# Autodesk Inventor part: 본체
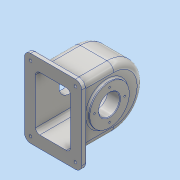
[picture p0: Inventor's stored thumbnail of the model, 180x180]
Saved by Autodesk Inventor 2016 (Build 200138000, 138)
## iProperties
Created: 2018-11
Part Number: 본체
Material: 알루미늄 6061
Document SubType Name: Modeling
Designer: user
Density: 2.7 g/cm^3
Appearance: 알루미늄 - 평지
Mass: 1136.18 g
Surface Area: 1200.87 cm^2
Volume: 420.806 cm^3
Author: user
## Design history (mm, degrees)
sketch "스케치1"
  geometry: L1 (-55, 75)-(55, 75); L2 (55, 75)-(55, -75); L3 (55, -75)-(-55, -75); L4 (-55, -75)-(-55, 75); L5 (-55, 75)-(55, -75); L6 (55, 75)-(-55, -75); 1 further point
  constraints: 12 end point, 2 midpoint, 2 parallel, 1 horizontal, 1 perpendicular
  dimensions: "d0" = 150 distance of L1.end L2.end; "d1" = 110 distance of L1.start L1.end
extrude "돌출1" new body sketch "스케치1" distance "d2" = 10; taper "d3" = 0 deg
node "작업 평면1"
sketch "스케치5"
  geometry: L1 (78, 58)-(10, 58); L2 (10, -75)-(10, 75) reference; L3 (78, -58)-(10, -58); A1 r 58 centre (78, 0) between (78, -58) and (78, 58); 1 further point
  constraints: 4 end point, 2 point on circle, 2 point on line, 2 tangent, 1 centre point, 1 horizontal, 1 horizontal alignment, 1 perpendicular
  dimensions: "d5" = 78 distance of point (0, 0) A1.centre; "d6" = 116 diameter of A1
extrude "돌출2" join sketch "스케치5" stored distance "d7" = 77; taper "d8" = 0 deg
sketch "스케치6"
  geometry: L1 (75, 0)-(-75, 0) reference; C1 r 38 at (0, 65); 2 further points
  constraints: 1 centre point, 1 midpoint, 1 vertical alignment
  dimensions: "d11" = 76 diameter of C1; "d12" = 65 distance from line of L1 C1.centre
extrude "돌출3" join sketch "스케치6" distance "d13" = 5; taper "d14" = 0 deg
sketch "스케치7"
  geometry: L1 (75, 0)-(-75, 0) reference; C1 r 38 at (0, 65); 2 further points
  constraints: 1 centre point, 1 midpoint, 1 vertical alignment
  dimensions: "d15" = 76 diameter of C1; "d16" = 65 distance from line of L1 C1.centre
extrude "돌출4" join sketch "스케치7" distance "d17" = 10; taper "d18" = 0 deg
sketch "스케치11"
  geometry: L1 (10, -58)-(78, -58) reference; L2 (78, 58)-(10, 58) reference; L3 (0, 52)-(78, 52); L4 (78, -52)-(0, -52); L5 (0, -75)-(0, 75) reference; L6 (0, -52)-(0, 52); A1 r 58 centre (78, 0) between (78, -58) and (78, 58) reference; A2 r 52 centre (78, 0) between (78, -52) and (78, 52); 1 further point
  constraints: 6 end point, 2 horizontal, 2 point on circle, 2 point on line, 2 tangent, 1 centre point, 1 collinear
  dimensions: "d31" = 6 radial gap between concentric circles of A1 A2
extrude "돌출6" cut sketch "스케치11" stored distance "d32" = 67; taper "d33" = 0 deg
sketch "스케치12"
  geometry: C1 r 20 at (0, 0); C2 r 38 at (0, 0) reference; 1 further point
  constraints: 1 centre point, 1 concentric
  dimensions: "d34" = 40 diameter of C1
extrude "돌출7" cut sketch "스케치12" distance "d35" = 24; taper "d36" = 0 deg
sketch "스케치13"
  geometry: C1 r 20 at (0, 0); C2 r 38 at (0, 0) reference; 1 further point
  constraints: 1 centre point, 1 concentric
  dimensions: "d37" = 40 diameter of C1
extrude "돌출8" cut sketch "스케치13" distance "d38" = 15; taper "d39" = 0 deg
node "작업 평면3"
sketch "스케치16"
  geometry: C1 r 6 at (0, 0); 1 further point
  constraints: 1 centre point, 1 coincident
  dimensions: "d42" = 12 diameter of C1
extrude "돌출9" join sketch "스케치16" stored distance "d43" = 15; taper "d44" = 5 deg
node "작업 평면4"
sketch "스케치18"
  geometry: C1 r 6 at (0, 0) reference; 1 further point
hole "구멍1" sketch "스케치18" at (0, 0) diameter "d47" = 4.459; stored, may be unused: countersink angle "d51" = 90 deg, drill point angle "d53" = 118 deg; dims "d48" = 10, "d49" = 4, "d50" = 2, "d52" = 30
sketch "스케치19" dims "d54" = 58
  geometry: C1 r 38 at (0, 0) reference; 3 further points
  constraints: 2 vertical alignment, 3 other
hole "구멍2" sketch "스케치19" at (0, 29) diameter "d55" = 3.242; stored, may be unused: countersink angle "d59" = 90 deg, drill point angle "d61" = 118 deg; dims "d56" = 8, "d57" = 4, "d58" = 2, "d60" = 10
fillet "모깎기1" dims "d76" = 12
sketch "스케치21"
  geometry: A1 r 12 centre (43, -63) between (43, -75) and (55, -63) reference; A2 r 12 centre (-43, -63) between (-55, -63) and (-43, -75) reference; A3 r 12 centre (-43, 63) between (-43, 75) and (-55, 63) reference; A4 r 12 centre (43, 63) between (55, 63) and (43, 75) reference; 1 further point
hole "구멍4" sketch "스케치21" at (43, 63), (-43, 63), (43, -63), (-43, -63) diameter "d77" = 5; stored, may be unused: countersink angle "d81" = 90 deg, drill point angle "d83" = 118 deg; dims "d78" = 8, "d79" = 12, "d80" = 4, "d82" = 10
fillet "모깎기2" dims "d84" = 3
fillet "모깎기3" dims "d85" = 13
sketch "스케치23"
  geometry: C1 r 28 at (0, 65); C2 r 20 at (0, 65) reference; 1 further point
  constraints: 1 centre point, 1 concentric
  dimensions: "d86" = 56 diameter of C1
extrude "돌출10" join sketch "스케치23" distance "d87" = 14; taper "d88" = 0 deg
feature "면 기울기2" dims angle "d89" = 40 deg
sketch "스케치24" dims "d90" = 58
  geometry: C1 r 39.747 at (0, 0) reference; 3 further points
  constraints: 2 vertical alignment, 1 coincident, 2 other
hole "구멍5" sketch "스케치24" at (0, 29) diameter "d91" = 3.242; stored, may be unused: countersink angle "d95" = 90 deg, drill point angle "d97" = 118 deg; dims "d92" = 8, "d93" = 12, "d94" = 4, "d96" = 10
fillet "모깎기4" dims "d101" = 3
fillet "모깎기5" dims "d102" = 3
fillet "모깎기6" dims "d103" = 8
fillet "모깎기7" dims "d104" = 3
chamfer "모따기1" distance "d105" = 1; stored, may be unused: second distance "d106" = 2, angle "d107" = 45 deg
chamfer "모따기2" distance "d108" = 1; stored, may be unused: second distance "d109" = 2, angle "d110" = 45 deg
sketch "스케치25"
  geometry: L1 (-13, 0)-(-13, -65) reference; L2 (68.5, -78)-(-17.5, -78) reference; 2 further points
  constraints: 1 other
  dimensions: "d111" = 38.5 distance from line of L1 point (25.5, -38); "d112" = 40 distance from line of L2 point (25.5, -38)
feature "엠보싱1" sketch "스케치25" dims "d113" = 0.5, "d114" = 0
node "솔리드1"
pattern_circular "원형 패턴1" dims angle "d63" = 360 deg
pattern_circular "원형 패턴3" dims angle "d99" = 360 deg
other parameters: "d4" = 0, "d41" = -142, "d45" = 126.75
